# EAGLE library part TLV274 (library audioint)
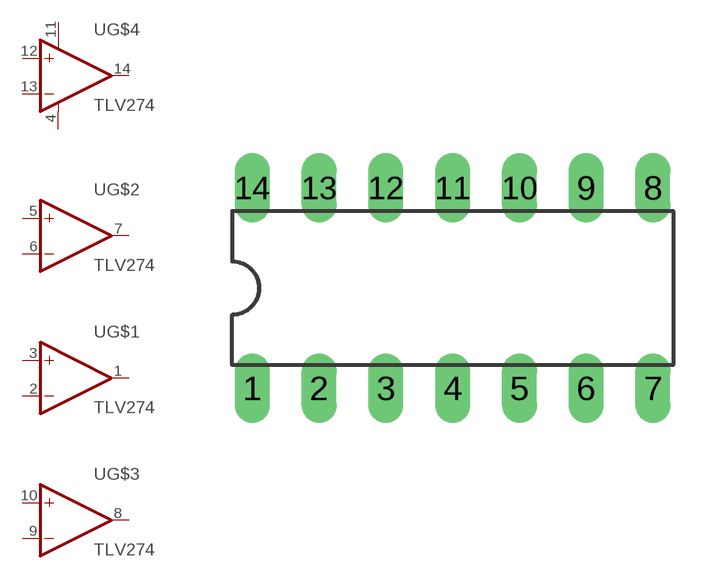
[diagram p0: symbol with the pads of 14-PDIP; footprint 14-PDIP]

Designator prefix -; gates G$1=OP-AMP G$2=OP-AMP G$3=OP-AMP G$4=OP-AMP-VCC

## TLV274  [14-PDIP]
1  G$1:OUT  out
2  G$1:-IN  in
3  G$1:+IN  in
4  G$4:V+  pwr
5  G$2:+IN  in
6  G$2:-IN  in
7  G$2:OUT  out
8  G$3:OUT  out
9  G$3:-IN  in
10  G$3:+IN  in
11  G$4:V-  pwr
12  G$4:+IN  in
13  G$4:-IN  in
14  G$4:OUT  out

## Footprint 14-PDIP (pad centres in mm)
drill 0.813 long: 1 -7.62,-3.81; 2 -5.08,-3.81; 3 -2.54,-3.81; 4 0,-3.81; 5 2.54,-3.81; 6 5.08,-3.81; 7 7.62,-3.81; 8 7.62,3.81; 9 5.08,3.81; 10 2.54,3.81; 11 0,3.81; 12 -2.54,3.81; 13 -5.08,3.81; 14 -7.62,3.81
